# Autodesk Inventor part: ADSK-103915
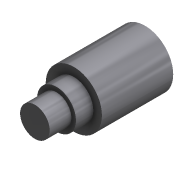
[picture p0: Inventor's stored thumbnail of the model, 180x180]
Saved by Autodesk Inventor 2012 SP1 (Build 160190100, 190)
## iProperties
Shininess: 0.0
Created: 2000-10
Part Number: ADSK-103915
Document SubType Name: Modeling
Stock Number: ADSK-103915
Density: 1 g/cm^3
Material: Default
Density: 0.0
Volumn: 0.0
Area: 0.0
PropertySet Name: Model Information
Control State: 0
Master: False
Checked Out: False
Author: gao
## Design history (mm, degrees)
node "Extrusion1" dims "d1" = 52.324, "d2" = 0
  sketch "Sketch1"
    geometry: C1 r 20.638 at (0, 0)
    constraints: 1 centre point
    dimensions: "d0" = 41.275 diameter of C1
node "Extrusion2" dims "d4" = 12.7, "d5" = 0
  sketch "Sketch2"
    geometry: C1 r 20.638 at (0, 0) reference; C2 r 14.287 at (0, 0)
    constraints: 1 centre point, 1 coincident
    dimensions: "d3" = 28.575 diameter of C2
node "Extrusion3" dims "d7" = 15.875, "d8" = 0
  sketch "Sketch3"
    geometry: C1 r 14.287 at (0, 0) reference; C2 r 10.871 at (0, 0)
    constraints: 1 centre point, 1 coincident
    dimensions: "d6" = 21.7424 diameter of C2
body "Solid1"
